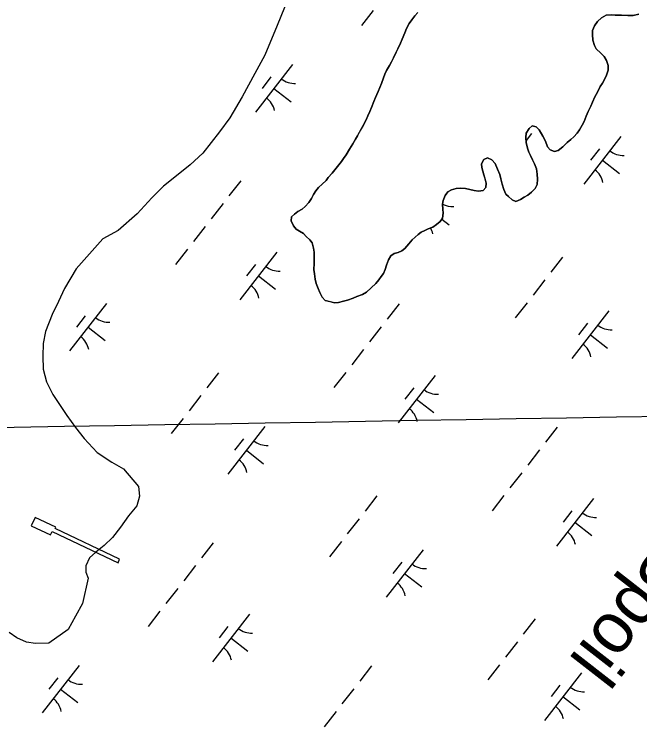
# Model space of a CAD drawing. Extents: x 3888273 to 3909528, y 158682 to 181032.
# Drawn here: x 3897459 to 3897978, y 168596 to 169187 of the extents above; entities that cross this region are included whole.
import ezdxf

# ---------------------------------------------------------------- set-up
doc = ezdxf.new("R2010")
doc.units = 0
for name, color, linetype in [('V-CHAN-DOCK', 7, 'Continuous'), ('V-CHAN-SPOL', 7, 'Continuous'), ('V-GRID-MAJR', 7, 'Continuous'), ('V-TOPO-SHOR', 7, 'Continuous'), ('V-WETL-SWMP', 7, 'Continuous')]:
    doc.layers.add(name, color=color, linetype=linetype)

msp = doc.modelspace()

# ---------------------------------------------------------------- linework, layer by layer
at = {"layer": 'V-CHAN-DOCK'}
msp.add_lwpolyline([(3897546.29, 168734.62), (3897492.77, 168759.97), (3897493.33, 168761.16), (3897476.23, 168769.26), (3897472.96, 168762.34), (3897489.01, 168754.74), (3897490.36, 168757.6), (3897545.07, 168731.68), (3897546.29, 168734.62)], dxfattribs=at)
at = {"layer": 'V-GRID-MAJR'}
msp.add_spline([(3893488.4, 168777.59), (3893877.65, 168784.1), (3899207.97, 168873.65), (3904538.27, 168963.98), (3905476.67, 168979.96)], degree=3, dxfattribs=at)
at = {"layer": 'V-TOPO-SHOR'}
for points in [[(3897793.77, 169188.07), (3897791.4, 169185.34), (3897788.83, 169182.03), (3897786.65, 169178.9), (3897784.27, 169174.61), (3897782.88, 169171.28), (3897780.68, 169165.8), (3897779.29, 169162.48), (3897777.1, 169157.98), (3897775.71, 169155.25), (3897773.52, 169150.55), (3897771.93, 169147.23), (3897770.14, 169144.11), (3897767.76, 169140), (3897766.37, 169136.87), (3897765.36, 169133.94), (3897763.76, 169129.05), (3897762.37, 169125.72), (3897760.97, 169122.4), (3897758.78, 169117.51), (3897757.38, 169114.18), (3897755.2, 169109.29), (3897754, 169105.97), (3897752.4, 169102.25), (3897751.01, 169098.93), (3897748.43, 169094.43), (3897746.04, 169090.14), (3897743.66, 169085.84), (3897742.07, 169083.1), (3897739.89, 169079.19), (3897737.11, 169074.7)], [(3897875.09, 169031.13), (3897879.02, 169032.87), (3897881.98, 169034.81), (3897885.13, 169036.55), (3897888.09, 169039.08), (3897891.05, 169042.01), (3897892.84, 169045.33), (3897893.07, 169049.84), (3897892.7, 169053.96), (3897892.15, 169058.47), (3897890.6, 169062.6), (3897888.86, 169065.95), (3897887.12, 169069.49), (3897885.77, 169072.24), (3897884.81, 169075.59), (3897883.66, 169080.3), (3897883.49, 169084.22), (3897883.71, 169087.95), (3897886.09, 169091.86), (3897888.66, 169094), (3897891.98, 169093.19), (3897894.52, 169090.62), (3897897.43, 169085.5), (3897899.56, 169081.37), (3897901.29, 169076.65), (3897903.63, 169074.09), (3897907.15, 169072.69), (3897910.29, 169073.65), (3897914.04, 169076.57), (3897917.79, 169080.07), (3897920.75, 169082.6), (3897923.12, 169084.94), (3897926.08, 169088.06), (3897927.86, 169090.59), (3897930.04, 169094.7), (3897931.63, 169097.63), (3897933.43, 169102.13), (3897935.03, 169105.85), (3897937.21, 169110.34), (3897938.61, 169113.66), (3897940.6, 169118.16), (3897942.78, 169122.07), (3897945.17, 169126.56), (3897946.95, 169129.49), (3897948.94, 169133.01), (3897950.33, 169136.14), (3897951.54, 169140.06), (3897951.56, 169143.98), (3897950.22, 169148.11), (3897948.48, 169151.65), (3897945.55, 169154.41), (3897941.85, 169157.77), (3897940.3, 169160.73), (3897938.96, 169165.05), (3897938.6, 169169.76), (3897938.81, 169173.09), (3897940.41, 169177.01), (3897942.79, 169180.52), (3897946.14, 169183.63), (3897950.08, 169185.76), (3897954.2, 169186.13), (3897957.53, 169185.91), (3897962.83, 169185.68), (3897968.12, 169185.64), (3897972.44, 169185.61), (3897977.15, 169186.56)], [(3897737.11, 169074.7), (3897734.33, 169070.01), (3897732.16, 169066.89), (3897730.37, 169064.35), (3897728.2, 169061.62), (3897722.66, 169054.71)], [(3897722.66, 169054.71), (3897719.5, 169051.21), (3897717.72, 169048.67), (3897714.36, 169045.75), (3897711.4, 169042.83), (3897709.22, 169040.1), (3897707.24, 169037.17), (3897705.65, 169033.65), (3897703.27, 169030.33), (3897700.31, 169027.01), (3897697.75, 169024.87), (3897694.2, 169022.94), (3897691.44, 169020.8), (3897689.07, 169018.46), (3897688.66, 169015.13), (3897690.59, 169011.2), (3897692.93, 169008.43), (3897695.66, 169006.65), (3897698.79, 169004.67), (3897701.12, 169002.3), (3897704.24, 168999.53), (3897706.19, 168996.97), (3897707.14, 168992.65), (3897707.71, 168989.31), (3897707.87, 168985.19), (3897707.84, 168979.89), (3897707.61, 168974.79), (3897707.97, 168971.26), (3897708.53, 168966.75), (3897709.49, 168963.21), (3897711.03, 168959.08), (3897712.38, 168955.93), (3897714.51, 168951.99), (3897716.85, 168949.23), (3897720.76, 168948.23), (3897724.68, 168947.22), (3897728.02, 168947.59), (3897732.14, 168948.74), (3897735.48, 168949.5), (3897740, 168951.04), (3897743.15, 168952.39), (3897747.87, 168954.12), (3897751.22, 168956.06), (3897755.16, 168959.57), (3897758.92, 168963.27), (3897761.49, 168966.39), (3897763.46, 168968.93), (3897765.25, 168971.66), (3897766.64, 168974.79), (3897767.84, 168978.51), (3897769.44, 168982.81), (3897771.43, 168986.13), (3897774.18, 168988.08), (3897777.53, 168989.03), (3897780.48, 168990.38), (3897783.04, 168992.33), (3897786.2, 168996.23), (3897789.17, 168999.54), (3897791.54, 169001.69), (3897794.1, 169003.83), (3897796.67, 169005.77), (3897799.62, 169007.32), (3897802.37, 169008.67), (3897806.11, 169010.02), (3897809.26, 169012.16), (3897812.22, 169014.69), (3897814.2, 169017.42), (3897814.82, 169021.73), (3897814.64, 169024.87), (3897814.28, 169028.99), (3897814.69, 169032.12), (3897816.48, 169036.23), (3897818.66, 169039.16), (3897821.61, 169040.9), (3897825.54, 169042.06), (3897828.88, 169042.42), (3897833.19, 169042.01), (3897836.91, 169041.19), (3897840.64, 169040.39), (3897844.16, 169039.77), (3897847.89, 169040.34), (3897850.07, 169042.87), (3897850.48, 169046.59), (3897849.53, 169049.93), (3897848.57, 169053.28), (3897847.8, 169056.42), (3897846.84, 169059.37), (3897846.47, 169062.51), (3897848.65, 169066.02), (3897851.61, 169067.57), (3897855.12, 169065.78), (3897857.85, 169062.83), (3897859.98, 169058.1), (3897861.71, 169053.58), (3897862.67, 169050.04), (3897863.62, 169045.72), (3897865.16, 169041.2), (3897866.9, 169037.46), (3897869.04, 169035.29), (3897872.16, 169032.72), (3897875.09, 169031.13)]]:
    msp.add_lwpolyline(points, dxfattribs=at)
at = {"layer": 'V-WETL-SWMP'}
for p, q in [((3897686.3, 169200.01), (3897677.16, 169177.36)), ((3897756.79, 169189.76), (3897746.96, 169177.13)), ((3897788.83, 169182.03), (3897791.4, 169185.34)), ((3897791.4, 169185.34), (3897793.78, 169188.08)), ((3897946.14, 169183.63), (3897942.79, 169180.52)), ((3897950.08, 169185.76), (3897946.14, 169183.63)), ((3897954.2, 169186.13), (3897950.08, 169185.76)), ((3897957.53, 169185.91), (3897954.2, 169186.13)), ((3897962.83, 169185.68), (3897957.53, 169185.91)), ((3897972.44, 169185.61), (3897962.83, 169185.68)), ((3897977.15, 169186.56), (3897972.44, 169185.61)), ((3897677.16, 169177.36), (3897666.76, 169152.72)), ((3897784.27, 169174.61), (3897786.65, 169178.9)), ((3897786.65, 169178.9), (3897788.83, 169182.03)), ((3897940.41, 169177), (3897938.81, 169173.09)), ((3897942.79, 169180.52), (3897940.41, 169177)), ((3897780.68, 169165.8), (3897782.88, 169171.28)), ((3897782.88, 169171.28), (3897784.27, 169174.61)), ((3897938.81, 169173.09), (3897938.6, 169169.76)), ((3897779.29, 169162.48), (3897780.68, 169165.8)), ((3897938.6, 169169.76), (3897938.96, 169165.05)), ((3897938.96, 169165.05), (3897940.3, 169160.73)), ((3897777.1, 169157.98), (3897779.29, 169162.48)), ((3897940.3, 169160.73), (3897941.85, 169157.77)), ((3897666.76, 169152.72), (3897658.42, 169137.55)), ((3897773.52, 169150.55), (3897775.71, 169155.25)), ((3897775.71, 169155.25), (3897777.1, 169157.98)), ((3897941.85, 169157.77), (3897945.55, 169154.41)), ((3897945.55, 169154.41), (3897948.48, 169151.65)), ((3897770.14, 169144.11), (3897771.93, 169147.23)), ((3897771.93, 169147.23), (3897773.52, 169150.55)), ((3897948.48, 169151.65), (3897950.22, 169148.11)), ((3897950.22, 169148.11), (3897951.56, 169143.98)), ((3897689.69, 169144.84), (3897658.99, 169105.37)), ((3897767.76, 169140), (3897770.14, 169144.11)), ((3897951.56, 169143.98), (3897951.54, 169140.06)), ((3897658.42, 169137.55), (3897648.06, 169118.15)), ((3897765.36, 169133.94), (3897766.36, 169136.87)), ((3897766.36, 169136.87), (3897767.76, 169140)), ((3897950.33, 169136.14), (3897948.94, 169133.01)), ((3897951.54, 169140.06), (3897950.33, 169136.14)), ((3897671.94, 169134.58), (3897664.57, 169125.11)), ((3897763.76, 169129.05), (3897765.36, 169133.94)), ((3897946.95, 169129.49), (3897945.17, 169126.56)), ((3897948.94, 169133.01), (3897946.95, 169129.49)), ((3897674.34, 169125.11), (3897688.55, 169114.05)), ((3897760.97, 169122.4), (3897763.76, 169129.05)), ((3897945.17, 169126.56), (3897942.78, 169122.07)), ((3897648.06, 169118.15), (3897637.71, 169100.75)), ((3897757.39, 169114.18), (3897758.78, 169117.51)), ((3897758.78, 169117.51), (3897760.97, 169122.4)), ((3897940.6, 169118.16), (3897938.61, 169113.67)), ((3897942.78, 169122.07), (3897940.6, 169118.16)), ((3897755.2, 169109.29), (3897757.39, 169114.18)), ((3897938.61, 169113.67), (3897937.21, 169110.34)), ((3897752.4, 169102.25), (3897754, 169105.97)), ((3897754, 169105.97), (3897755.2, 169109.29)), ((3897935.02, 169105.84), (3897933.43, 169102.13)), ((3897937.21, 169110.34), (3897935.02, 169105.84)), ((3897637.71, 169100.75), (3897629.14, 169089.08)), ((3897751.01, 169098.93), (3897752.4, 169102.25)), ((3897933.43, 169102.13), (3897931.64, 169097.63)), ((3897743.66, 169085.84), (3897748.43, 169094.43)), ((3897748.43, 169094.43), (3897751.01, 169098.93)), ((3897888.66, 169094), (3897886.09, 169091.86)), ((3897891.99, 169093.19), (3897888.66, 169094)), ((3897930.05, 169094.7), (3897927.86, 169090.59)), ((3897931.64, 169097.63), (3897930.05, 169094.7)), ((3897629.14, 169089.08), (3897615.29, 169071.45)), ((3897883.71, 169087.95), (3897883.49, 169084.23)), ((3897886.09, 169091.86), (3897883.71, 169087.95)), ((3897894.52, 169090.62), (3897891.99, 169093.19)), ((3897897.43, 169085.5), (3897894.52, 169090.62)), ((3897926.08, 169088.06), (3897923.12, 169084.94)), ((3897927.86, 169090.59), (3897926.08, 169088.06)), ((3897739.89, 169079.19), (3897742.07, 169083.1)), ((3897742.07, 169083.1), (3897743.66, 169085.84)), ((3897883.49, 169084.23), (3897883.66, 169080.3)), ((3897888.07, 169087.61), (3897883.59, 169081.86)), ((3897899.56, 169081.37), (3897897.43, 169085.5)), ((3897920.75, 169082.6), (3897917.79, 169080.07)), ((3897923.12, 169084.94), (3897920.75, 169082.6)), ((3897962.21, 169085.14), (3897931.51, 169045.68)), ((3897737.11, 169074.7), (3897739.89, 169079.19)), ((3897883.66, 169080.3), (3897884.81, 169075.59)), ((3897901.29, 169076.65), (3897899.56, 169081.37)), ((3897903.62, 169074.09), (3897901.29, 169076.65)), ((3897914.04, 169076.57), (3897910.29, 169073.65)), ((3897917.79, 169080.07), (3897914.04, 169076.57)), ((3897615.29, 169071.45), (3897605, 169061.79)), ((3897732.16, 169066.89), (3897734.33, 169070.01)), ((3897734.33, 169070.01), (3897737.11, 169074.7)), ((3897884.81, 169075.59), (3897885.77, 169072.25)), ((3897885.77, 169072.25), (3897888.86, 169065.95)), ((3897907.15, 169072.69), (3897903.62, 169074.09)), ((3897910.29, 169073.65), (3897907.15, 169072.69)), ((3897944.46, 169074.88), (3897937.09, 169065.41)), ((3897728.2, 169061.62), (3897730.37, 169064.35)), ((3897730.37, 169064.35), (3897732.16, 169066.89)), ((3897848.65, 169066.02), (3897846.47, 169062.51)), ((3897851.61, 169067.57), (3897848.65, 169066.02)), ((3897855.12, 169065.78), (3897851.61, 169067.57)), ((3897857.85, 169062.82), (3897855.12, 169065.78)), ((3897888.86, 169065.95), (3897890.6, 169062.6)), ((3897946.86, 169065.41), (3897961.07, 169054.36)), ((3897605, 169061.79), (3897594.96, 169053.62)), ((3897722.66, 169054.71), (3897728.2, 169061.62)), ((3897846.47, 169062.51), (3897846.84, 169059.37)), ((3897846.84, 169059.37), (3897847.8, 169056.42)), ((3897859.98, 169058.1), (3897857.85, 169062.82)), ((3897890.6, 169062.6), (3897892.14, 169058.47)), ((3897892.14, 169058.47), (3897892.7, 169053.96)), ((3897594.96, 169053.62), (3897582.66, 169043.97)), ((3897719.5, 169051.21), (3897722.66, 169054.71)), ((3897847.8, 169056.42), (3897848.57, 169053.28)), ((3897848.57, 169053.28), (3897850.48, 169046.59)), ((3897861.71, 169053.58), (3897859.98, 169058.1)), ((3897862.67, 169050.04), (3897861.71, 169053.58)), ((3897892.7, 169053.96), (3897893.07, 169049.84)), ((3897646.9, 169048.52), (3897637.07, 169035.89)), ((3897714.36, 169045.75), (3897717.72, 169048.67)), ((3897717.72, 169048.67), (3897719.5, 169051.21)), ((3897850.48, 169046.59), (3897850.07, 169042.87)), ((3897863.62, 169045.72), (3897862.67, 169050.04)), ((3897893.07, 169049.84), (3897892.84, 169045.33)), ((3897582.66, 169043.97), (3897573.11, 169034.3)), ((3897709.22, 169040.1), (3897711.4, 169042.83)), ((3897711.4, 169042.83), (3897714.36, 169045.75)), ((3897821.61, 169040.9), (3897818.66, 169039.16)), ((3897825.54, 169042.06), (3897821.61, 169040.9)), ((3897828.88, 169042.43), (3897825.54, 169042.06)), ((3897833.19, 169042), (3897828.88, 169042.43)), ((3897840.64, 169040.39), (3897833.19, 169042)), ((3897850.07, 169042.87), (3897847.89, 169040.34)), ((3897865.16, 169041.2), (3897863.62, 169045.72)), ((3897866.9, 169037.46), (3897865.16, 169041.2)), ((3897891.05, 169042.01), (3897888.09, 169039.08)), ((3897892.84, 169045.33), (3897891.05, 169042.01)), ((3897705.65, 169033.65), (3897707.24, 169037.17)), ((3897707.24, 169037.17), (3897709.22, 169040.1)), ((3897816.48, 169036.23), (3897814.69, 169032.13)), ((3897818.66, 169039.16), (3897816.48, 169036.23)), ((3897844.16, 169039.77), (3897840.64, 169040.39)), ((3897847.89, 169040.34), (3897844.16, 169039.77)), ((3897869.04, 169035.29), (3897866.9, 169037.46)), ((3897872.16, 169032.72), (3897869.04, 169035.29)), ((3897881.98, 169034.81), (3897879.03, 169032.87)), ((3897885.13, 169036.55), (3897881.98, 169034.81)), ((3897888.09, 169039.08), (3897885.13, 169036.55)), ((3897573.11, 169034.3), (3897560.79, 169020.91)), ((3897632.16, 169029.58), (3897622.33, 169016.95)), ((3897700.31, 169027.01), (3897703.27, 169030.33)), ((3897703.27, 169030.33), (3897705.65, 169033.65)), ((3897814.69, 169032.13), (3897814.28, 169028.99)), ((3897814.28, 169028.99), (3897814.64, 169024.87)), ((3897875.09, 169031.13), (3897872.16, 169032.72)), ((3897879.03, 169032.87), (3897875.09, 169031.13)), ((3897691.44, 169020.8), (3897694.2, 169022.94)), ((3897694.2, 169022.94), (3897697.75, 169024.87)), ((3897697.75, 169024.87), (3897700.31, 169027.01)), ((3897814.64, 169024.87), (3897814.82, 169021.73)), ((3897560.79, 169020.91), (3897545.22, 169007.29)), ((3897688.66, 169015.13), (3897689.07, 169018.46)), ((3897689.07, 169018.46), (3897691.44, 169020.8)), ((3897814.2, 169017.42), (3897812.22, 169014.69)), ((3897814.82, 169021.73), (3897814.2, 169017.42)), ((3897690.59, 169011.19), (3897688.66, 169015.13)), ((3897692.93, 169008.43), (3897690.59, 169011.19)), ((3897809.26, 169012.16), (3897806.11, 169010.02)), ((3897812.22, 169014.69), (3897809.26, 169012.16)), ((3897813.67, 169016.7), (3897819.83, 169011.91)), ((3897545.22, 169007.29), (3897532.45, 169000.39)), ((3897617.42, 169010.64), (3897607.6, 168998.01)), ((3897695.66, 169006.65), (3897692.93, 169008.43)), ((3897698.79, 169004.67), (3897695.66, 169006.65)), ((3897796.66, 169005.77), (3897794.1, 169003.83)), ((3897799.62, 169007.32), (3897796.66, 169005.77)), ((3897802.37, 169008.67), (3897799.62, 169007.32)), ((3897806.11, 169010.02), (3897802.37, 169008.67)), ((3897532.45, 169000.39), (3897510.31, 168975.33)), ((3897701.12, 169002.3), (3897698.79, 169004.67)), ((3897704.24, 168999.53), (3897701.12, 169002.3)), ((3897706.19, 168996.97), (3897704.24, 168999.53)), ((3897789.17, 168999.54), (3897786.2, 168996.23)), ((3897791.54, 169001.69), (3897789.17, 168999.54)), ((3897794.1, 169003.83), (3897791.54, 169001.69)), ((3897707.14, 168992.64), (3897706.19, 168996.97)), ((3897786.2, 168996.23), (3897783.04, 168992.33)), ((3897602.68, 168991.7), (3897592.86, 168979.07)), ((3897676.83, 168989.22), (3897646.12, 168949.76)), ((3897707.71, 168989.31), (3897707.14, 168992.64)), ((3897707.87, 168985.19), (3897707.71, 168989.31)), ((3897774.19, 168988.07), (3897771.43, 168986.13)), ((3897777.53, 168989.03), (3897774.19, 168988.07)), ((3897780.48, 168990.38), (3897777.53, 168989.03)), ((3897783.04, 168992.33), (3897780.48, 168990.38)), ((3897707.84, 168979.89), (3897707.87, 168985.19)), ((3897769.44, 168982.81), (3897767.84, 168978.51)), ((3897771.43, 168986.13), (3897769.44, 168982.81)), ((3897913.89, 168985.23), (3897904.06, 168972.6)), ((3897659.07, 168978.96), (3897651.7, 168969.49)), ((3897707.61, 168974.79), (3897707.84, 168979.89)), ((3897767.84, 168978.51), (3897766.64, 168974.79)), ((3897510.31, 168975.33), (3897500.72, 168959.17)), ((3897707.98, 168971.26), (3897707.61, 168974.79)), ((3897708.53, 168966.75), (3897707.98, 168971.26)), ((3897765.25, 168971.66), (3897763.46, 168968.93)), ((3897766.64, 168974.79), (3897765.25, 168971.66)), ((3897661.48, 168969.49), (3897675.68, 168958.44)), ((3897709.49, 168963.21), (3897708.53, 168966.75)), ((3897761.49, 168966.39), (3897758.92, 168963.27)), ((3897763.46, 168968.93), (3897761.49, 168966.39)), ((3897899.15, 168966.29), (3897889.33, 168953.66)), ((3897500.72, 168959.17), (3897495.65, 168948.22)), ((3897711.03, 168959.08), (3897709.49, 168963.21)), ((3897712.38, 168955.93), (3897711.03, 168959.08)), ((3897755.16, 168959.57), (3897751.22, 168956.06)), ((3897758.92, 168963.27), (3897755.16, 168959.57)), ((3897714.51, 168952), (3897712.38, 168955.93)), ((3897716.85, 168949.24), (3897714.51, 168952)), ((3897743.15, 168952.39), (3897740, 168951.04)), ((3897747.87, 168954.12), (3897743.15, 168952.39)), ((3897751.22, 168956.06), (3897747.87, 168954.12)), ((3897495.65, 168948.22), (3897490.34, 168937.53)), ((3897535.59, 168946.77), (3897504.88, 168907.31)), ((3897724.68, 168947.22), (3897716.85, 168949.24)), ((3897728.02, 168947.59), (3897724.68, 168947.22)), ((3897732.14, 168948.74), (3897728.02, 168947.59)), ((3897735.48, 168949.5), (3897732.14, 168948.74)), ((3897740, 168951.04), (3897735.48, 168949.5)), ((3897778.18, 168946.38), (3897768.35, 168933.75)), ((3897884.41, 168947.34), (3897874.59, 168934.72)), ((3897952.25, 168940.55), (3897921.55, 168901.09)), ((3897490.34, 168937.53), (3897485, 168923.34)), ((3897517.83, 168936.52), (3897510.46, 168927.04)), ((3897934.5, 168930.29), (3897927.13, 168920.82)), ((3897485, 168923.34), (3897482.94, 168913.62)), ((3897520.23, 168927.04), (3897534.44, 168915.99)), ((3897763.44, 168927.43), (3897753.62, 168914.81)), ((3897936.9, 168920.82), (3897951.11, 168909.76)), ((3897482.94, 168913.62), (3897482.62, 168902.89)), ((3897748.7, 168908.49), (3897738.88, 168895.86)), ((3897482.62, 168902.89), (3897483.04, 168892.15)), ((3897483.04, 168892.15), (3897485.72, 168881.65)), ((3897628.5, 168889.31), (3897618.68, 168876.68)), ((3897733.96, 168889.55), (3897724.14, 168876.92)), ((3897808.11, 168887.08), (3897777.4, 168847.62)), ((3897485.72, 168881.65), (3897490.89, 168871.13)), ((3897790.35, 168876.82), (3897782.98, 168867.35)), ((3897490.89, 168871.13), (3897502.5, 168853.83)), ((3897613.76, 168870.37), (3897603.94, 168857.74)), ((3897792.76, 168867.35), (3897806.96, 168856.29)), ((3897502.5, 168853.83), (3897509.67, 168843.8)), ((3897599.03, 168851.42), (3897589.2, 168838.8)), ((3897509.67, 168843.8), (3897517.09, 168834.77)), ((3897666.87, 168844.63), (3897636.16, 168805.17)), ((3897909.46, 168844.23), (3897899.63, 168831.6)), ((3897517.09, 168834.77), (3897527.75, 168823.21)), ((3897649.11, 168834.37), (3897641.74, 168824.9)), ((3897527.75, 168823.21), (3897539.92, 168815.14)), ((3897651.51, 168824.9), (3897665.72, 168813.84)), ((3897894.72, 168825.29), (3897884.9, 168812.66)), ((3897539.92, 168815.14), (3897549.62, 168809.58)), ((3897549.62, 168809.58), (3897562, 168795.02)), ((3897879.98, 168806.35), (3897870.16, 168793.72)), ((3897562, 168795.02), (3897562.94, 168786.78)), ((3897562.94, 168786.78), (3897560.64, 168778.81)), ((3897759.78, 168787.16), (3897749.96, 168774.54)), ((3897865.25, 168787.41), (3897855.42, 168774.78)), ((3897939.39, 168784.93), (3897908.68, 168745.47)), ((3897560.64, 168778.81), (3897553.85, 168770.62)), ((3897921.63, 168774.68), (3897914.26, 168765.2)), ((3897553.85, 168770.62), (3897547.04, 168761.18)), ((3897745.04, 168768.22), (3897735.22, 168755.59)), ((3897924.04, 168765.2), (3897938.24, 168754.15)), ((3897547.04, 168761.18), (3897540.5, 168752.49)), ((3897540.5, 168752.49), (3897533.46, 168746.05)), ((3897533.46, 168746.05), (3897526.69, 168740.36)), ((3897624.07, 168748.31), (3897614.25, 168735.68)), ((3897730.31, 168749.28), (3897720.48, 168736.65)), ((3897526.69, 168740.36), (3897521.41, 168735.65)), ((3897798.15, 168742.48), (3897767.44, 168703.02)), ((3897521.41, 168735.65), (3897518.37, 168729.18)), ((3897518.37, 168729.18), (3897518.34, 168723.94)), ((3897609.33, 168729.37), (3897599.51, 168716.74)), ((3897780.39, 168732.23), (3897773.02, 168722.76)), ((3897518.34, 168723.94), (3897520.3, 168718.93)), ((3897782.8, 168722.75), (3897797, 168711.7)), ((3897520.3, 168718.93), (3897515.67, 168698)), ((3897594.6, 168710.43), (3897584.77, 168697.8)), ((3897515.67, 168698), (3897509.85, 168687.31)), ((3897509.85, 168687.31), (3897503.79, 168676.37)), ((3897579.86, 168691.49), (3897570.03, 168678.86)), ((3897654, 168689.01), (3897623.3, 168649.55)), ((3897891.06, 168685.02), (3897881.24, 168672.39)), ((3897503.79, 168676.37), (3897487.74, 168665)), ((3897636.24, 168678.76), (3897628.88, 168669.29)), ((3897461.06, 168669.42), (3897454.6, 168673.71)), ((3897469.02, 168665.87), (3897461.06, 168669.42)), ((3897638.65, 168669.28), (3897652.86, 168658.23)), ((3897476.5, 168664.57), (3897469.02, 168665.87)), ((3897487.74, 168665), (3897476.5, 168664.57)), ((3897876.33, 168666.08), (3897866.5, 168653.45)), ((3897512.76, 168646.57), (3897482.06, 168607.1)), ((3897755.35, 168646.17), (3897745.53, 168633.54)), ((3897861.59, 168647.14), (3897851.76, 168634.51)), ((3897929.43, 168640.34), (3897898.72, 168600.88)), ((3897495, 168636.31), (3897487.63, 168626.84)), ((3897497.41, 168626.83), (3897511.61, 168615.78)), ((3897740.62, 168627.23), (3897730.79, 168614.6)), ((3897911.67, 168630.08), (3897904.3, 168620.61)), ((3897914.08, 168620.61), (3897928.28, 168609.55)), ((3897725.88, 168608.28), (3897716.05, 168595.66))]:
    msp.add_line(p, q, dxfattribs=at)
for centre, start, end in [((3897691.49, 169146.76), 231.34298, 272.88664), ((3897657.57, 169103.16), 11.34298, 52.88663), ((3897964.01, 169087.06), 231.34298, 272.88664), ((3897930.09, 169043.46), 11.34298, 52.88663), ((3897822.77, 169044.62), 241.27233, 272.88664), ((3897788.85, 169001.02), 11.34298, 28.3678), ((3897678.62, 168991.15), 231.34298, 272.88664), ((3897644.7, 168947.55), 11.34298, 52.88663), ((3897537.38, 168948.7), 231.34298, 272.88664), ((3897954.05, 168942.47), 231.34298, 272.88664), ((3897503.46, 168905.1), 11.34298, 52.88663), ((3897920.13, 168898.87), 11.34298, 52.88663), ((3897809.9, 168889), 231.34298, 272.88664), ((3897775.98, 168845.4), 11.34298, 52.88663), ((3897668.66, 168846.55), 231.34298, 272.88664), ((3897634.74, 168802.95), 11.34298, 52.88663), ((3897941.19, 168786.86), 231.34298, 272.88664), ((3897907.26, 168743.26), 11.34298, 52.88663), ((3897799.94, 168744.41), 231.34298, 272.88664), ((3897766.02, 168700.81), 11.34298, 52.88663), ((3897655.8, 168690.94), 231.34298, 272.88664), ((3897621.88, 168647.34), 11.34298, 52.88663), ((3897514.56, 168648.49), 231.34298, 272.88664), ((3897931.23, 168642.26), 231.34298, 272.88664), ((3897480.63, 168604.89), 11.34298, 52.88663), ((3897897.3, 168598.66), 11.34298, 52.88663)]:
    msp.add_arc(centre, 17.62, start, end, dxfattribs=at)

# ---------------------------------------------------------------- texts
at = {"layer": 'V-CHAN-SPOL'}
msp.add_text('Spoil', height=42, rotation=232.11852, dxfattribs=at).set_placement((3897994.69, 168749.91))

doc.saveas('drawing.dxf')
